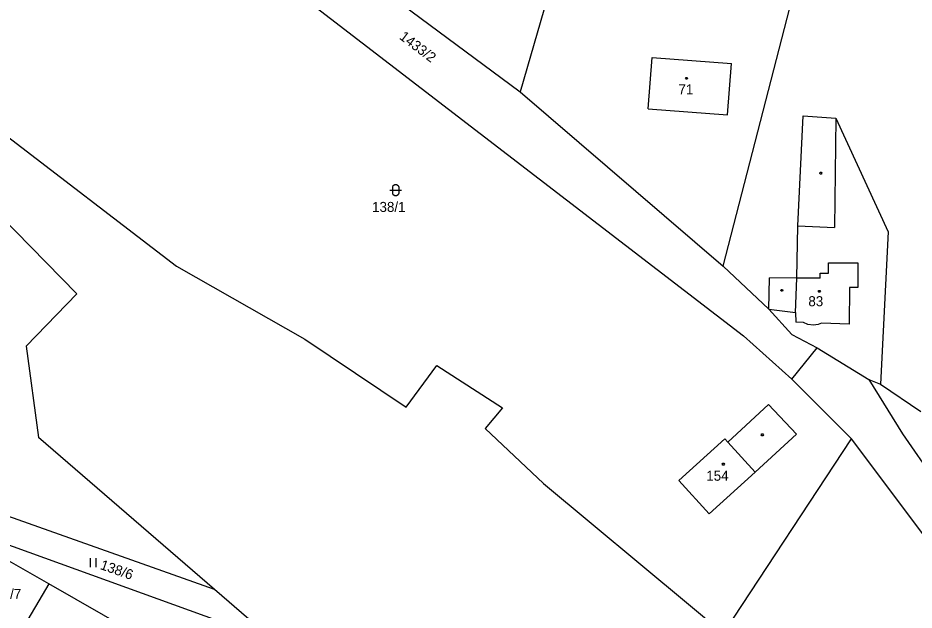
# Model space of a CAD drawing. Extents: x -852001 to -842497, y -1063614 to -1052182.
# Drawn here: x -849276.2 to -849124, y -1056124 to -1056023.5 of the extents above; entities that cross this region are included whole.
import ezdxf

# ---------------------------------------------------------------- set-up
doc = ezdxf.new("R2010")
doc.units = 0
for name, color, linetype in [('Default', 7, 'Continuous'), ('KN_HRANICE', 7, 'Continuous'), ('KN_KULTURY', 7, 'Continuous'), ('KN_PARCELY', 7, 'Continuous'), ('KN_SLUCKY', 7, 'Continuous')]:
    doc.layers.add(name, color=color, linetype=linetype)

# ---------------------------------------------------------------- blocks, each defined once
blk = doc.blocks.new('306')
at = {"layer": 'Default'}
for p, q in [((-0.5, 1.5), (-0.5, 0)), ((0.5, 0), (0.5, 1.5))]:
    blk.add_line(p, q, dxfattribs=at)
blk = doc.blocks.new('316')
at = {"layer": 'Default'}
for points in [[(-0.5, 1.5), (-0.4, 1.79), (-0.15, 1.97), (0.16, 1.97), (0.41, 1.79), (0.51, 1.5), (0.51, 0.5), (0.41, 0.21), (0.16, 0.03), (-0.15, 0.03), (-0.4, 0.21), (-0.5, 0.5), (-0.5, 1.5)], [(-1, 1), (0.27, 1), (1, 1)]]:
    blk.add_lwpolyline(points, dxfattribs=at)
blk = doc.blocks.new('NAHRADNI_SYMBOL')
at = {"layer": 'Default'}
blk.add_lwpolyline([(0.09, 0.15), (0.18, 0), (0.09, -0.15), (-0.09, -0.15), (-0.18, 0), (-0.09, 0.15), (0.09, 0.15)], dxfattribs=at)
blk = doc.blocks.new('402')
at = {"layer": 'Default'}
blk.add_lwpolyline([(0.09, 0.15), (0.18, 0), (0.09, -0.15), (-0.09, -0.15), (-0.18, 0), (-0.09, 0.15), (0.09, 0.15)], dxfattribs=at)

msp = doc.modelspace()

# ---------------------------------------------------------------- linework, layer by layer
at = {"layer": 'KN_HRANICE'}
for p, q in [((-849181.16, -1056002.47), (-849190.94, -1056036.05)), ((-849244.77, -1056006.91), (-849153.01, -1056077.46)), ((-849222.2, -1056012.85), (-849190.94, -1056036.05)), ((-849156.44, -1056065.63), (-849143.94, -1056017.04)), ((-849169.18, -1056038.94), (-849168.51, -1056030.22)), ((-849168.51, -1056030.22), (-849155.05, -1056031.25)), ((-849155.72, -1056039.97), (-849155.05, -1056031.25)), ((-849287.32, -1056036.5), (-849249.28, -1056065.66)), ((-849190.94, -1056036.05), (-849156.44, -1056065.63)), ((-849169.18, -1056038.94), (-849155.72, -1056039.97)), ((-849143.77, -1056058.77), (-849142.84, -1056040.13)), ((-849142.84, -1056040.13), (-849137.29, -1056040.5)), ((-849137.29, -1056040.5), (-849128.44, -1056059.8)), ((-849279.23, -1056057.01), (-849266.21, -1056070.35)), ((-849143.92, -1056067.66), (-849143.77, -1056058.77)), ((-849128.44, -1056059.8), (-849129.75, -1056085.67)), ((-849249.28, -1056065.66), (-849227.51, -1056078.03)), ((-849148.67, -1056072.93), (-849156.44, -1056065.63)), ((-849148.67, -1056072.93), (-849148.6, -1056067.65)), ((-849143.92, -1056067.66), (-849148.6, -1056067.65)), ((-849266.21, -1056070.35), (-849274.84, -1056079.2)), ((-849148.67, -1056072.93), (-849144.79, -1056077.26)), ((-849153.01, -1056077.46), (-849144.79, -1056084.84)), ((-849144.79, -1056077.26), (-849140.51, -1056079.49)), ((-849274.84, -1056079.2), (-849272.71, -1056094.76)), ((-849227.51, -1056078.03), (-849210.29, -1056089.59)), ((-849144.79, -1056084.84), (-849140.51, -1056079.49)), ((-849140.51, -1056079.49), (-849131.69, -1056084.88)), ((-849210.29, -1056089.59), (-849205.06, -1056082.5)), ((-849205.06, -1056082.5), (-849193.95, -1056089.69)), ((-849144.79, -1056084.84), (-849134.65, -1056094.95)), ((-849131.69, -1056084.88), (-849129.75, -1056085.67)), ((-849131.69, -1056084.88), (-849125.98, -1056094.1)), ((-849129.75, -1056085.67), (-849122.9, -1056090.32)), ((-849193.95, -1056089.69), (-849196.89, -1056093.18)), ((-849155.67, -1056095.51), (-849148.74, -1056089.13)), ((-849148.74, -1056089.13), (-849144.01, -1056094.18)), ((-849196.89, -1056093.18), (-849186.98, -1056102.56)), ((-849144.01, -1056094.18), (-849151.02, -1056100.61)), ((-849125.98, -1056094.1), (-849108.8, -1056119.1)), ((-849242.85, -1056120.56), (-849272.71, -1056094.76)), ((-849164, -1056102.05), (-849156.19, -1056094.94)), ((-849156.39, -1056127.95), (-849134.65, -1056094.95)), ((-849156.19, -1056094.94), (-849155.67, -1056095.51)), ((-849113.79, -1056122.8), (-849134.65, -1056094.95)), ((-849158.83, -1056107.72), (-849164, -1056102.05)), ((-849151.02, -1056100.61), (-849158.83, -1056107.72)), ((-849186.98, -1056102.56), (-849162.35, -1056123.05)), ((-849242.85, -1056120.56), (-849283.48, -1056106.16)), ((-849282.78, -1056111.19), (-849239.16, -1056126.97)), ((-849270.99, -1056119.57), (-849282.53, -1056112.97)), ((-849270.99, -1056119.57), (-849275.8, -1056127.79)), ((-849256.82, -1056127.68), (-849270.99, -1056119.57)), ((-849236.99, -1056125.61), (-849242.85, -1056120.56)), ((-849162.35, -1056123.05), (-849156.39, -1056127.95))]:
    msp.add_line(p, q, dxfattribs=at)
at = {"layer": 'KN_SLUCKY'}
for p, q in [((-849137.29, -1056040.5), (-849137.52, -1056059.05)), ((-849143.77, -1056058.77), (-849137.52, -1056059.05)), ((-849138.57, -1056066.85), (-849138.56, -1056065.07)), ((-849138.56, -1056065.07), (-849133.56, -1056065.08)), ((-849133.56, -1056065.08), (-849133.57, -1056069.28)), ((-849140, -1056067.67), (-849140, -1056066.85)), ((-849140, -1056066.85), (-849138.57, -1056066.85)), ((-849144.16, -1056073.51), (-849143.92, -1056067.66)), ((-849140, -1056067.67), (-849143.92, -1056067.66)), ((-849134.99, -1056069.28), (-849135.03, -1056075.5)), ((-849133.57, -1056069.28), (-849134.99, -1056069.28)), ((-849148.67, -1056072.93), (-849144.16, -1056073.51)), ((-849144.16, -1056073.51), (-849144.09, -1056075.16)), ((-849142.81, -1056075.18), (-849144.09, -1056075.16)), ((-849142.05, -1056075.54), (-849142.81, -1056075.18)), ((-849141.09, -1056075.68), (-849142.05, -1056075.54)), ((-849140.34, -1056075.56), (-849141.09, -1056075.68)), ((-849139.73, -1056075.31), (-849140.34, -1056075.56)), ((-849135.03, -1056075.5), (-849139.73, -1056075.31)), ((-849155.67, -1056095.51), (-849151.02, -1056100.61))]:
    msp.add_line(p, q, dxfattribs=at)

# ---------------------------------------------------------------- block references
at = {"layer": 'KN_KULTURY'}
for name, p in [('NAHRADNI_SYMBOL', (-849162.67, -1056033.76)), ('402', (-849139.87, -1056049.85)), ('316', (-849212.07, -1056053.73)), ('402', (-849146.48, -1056069.76)), ('402', (-849140.12, -1056069.92)), ('402', (-849149.8, -1056094.28)), ('402', (-849156.42, -1056099.26)), ('306', (-849263.43, -1056116.73))]:
    msp.add_blockref(name, p, dxfattribs=at)

# ---------------------------------------------------------------- texts
at = {"layer": 'KN_PARCELY'}
for s, rotation, p in [('1433/2', 322.747, (-849211.57, -1056026.95)), ('138/6', 340.738, (-849262.38, -1056117.05))]:
    msp.add_text(s, height=1.7, rotation=rotation, dxfattribs=at).set_placement(p)
for s, p in [('71', (-849164.05, -1056036.46)), ('138/1', (-849216.08, -1056056.43)), ('83', (-849141.98, -1056072.44)), ('154', (-849159.32, -1056102.08)), ('138/7', (-849281.35, -1056122.16))]:
    msp.add_text(s, height=1.7, dxfattribs=at).set_placement(p)

doc.saveas('drawing.dxf')
